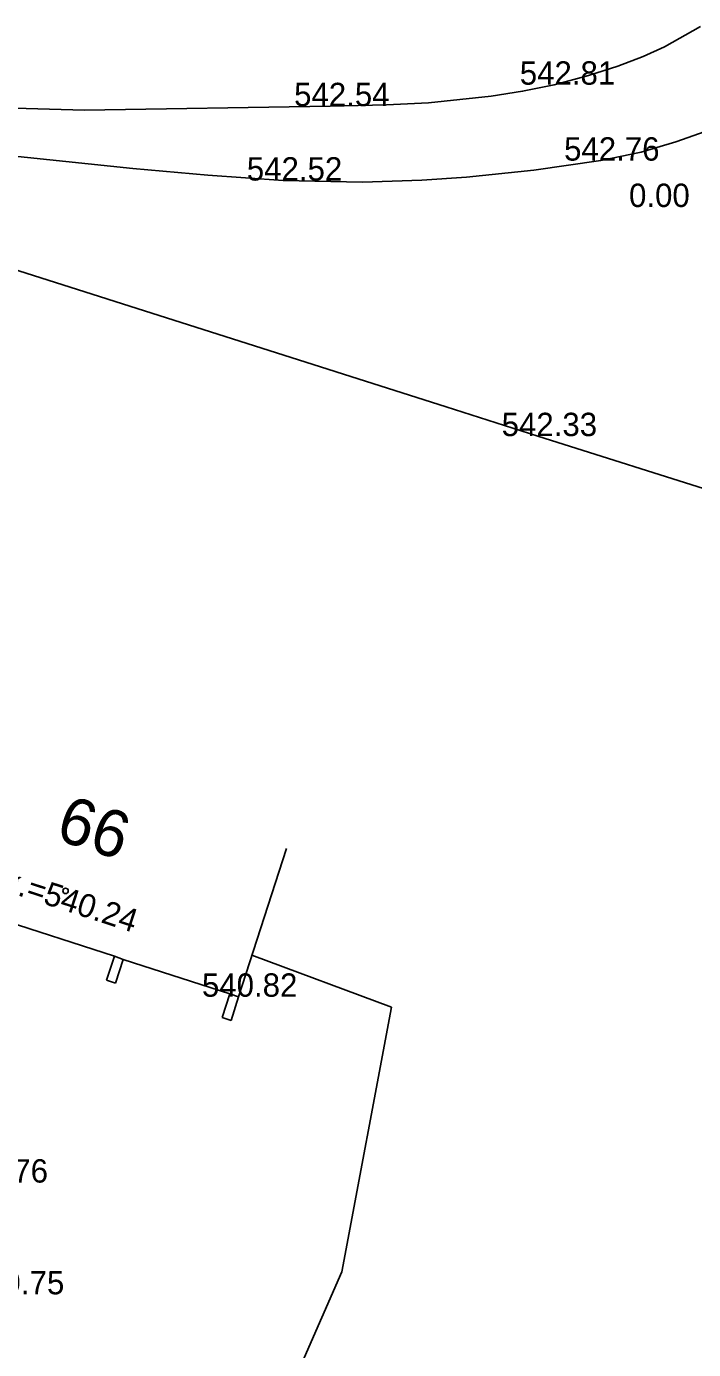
# Model space of a CAD drawing. Extents: x -669393 to -668650, y -1126925 to -1126294.
# Drawn here: x -669060.59 to -669039.15, y -1126670.25 to -1126627.75 of the extents above; entities that cross this region are included whole.
import ezdxf

# ---------------------------------------------------------------- set-up
doc = ezdxf.new("R2010")
doc.units = 0
for name, color, linetype in [('G_Bod_tecka', 7, 'Continuous'), ('G_Bod_vyska', 7, 'Continuous'), ('G_Budovy-znacky', 7, 'Continuous'), ('G_Budovy_Objekty', 7, 'Continuous'), ('G_Budovy_vstupy', 7, 'Continuous'), ('G_Cesty_Schody', 7, 'Continuous'), ('G_Cisla_orientacni', 7, 'Continuous'), ('G_Ploty', 7, 'Continuous'), ('G_Poznamky_odkaz', 7, 'Continuous'), ('G_Z_SPOJE_podz_geodeticky', 7, 'Continuous'), ('G_Z_SPOJE_podz_kotovane', 7, 'Continuous'), ('G_Z_SPOJE_podz_priblizne', 7, 'Continuous')]:
    doc.layers.add(name, color=color, linetype=linetype)

msp = doc.modelspace()

# ---------------------------------------------------------------- linework, layer by layer
at = {"layer": 'G_Bod_tecka'}
for p, q in [((-669043.63, -1126629.62), (-669043.63, -1126629.62)), ((-669050.82, -1126630.31), (-669050.82, -1126630.31)), ((-669042.13, -1126632.06), (-669042.13, -1126632.06)), ((-669052.34, -1126632.7), (-669052.34, -1126632.7)), ((-669040.44, -1126633.55), (-669040.44, -1126633.55)), ((-669044.15, -1126640.91), (-669044.15, -1126640.91)), ((-669053.77, -1126658.92), (-669053.77, -1126658.92))]:
    msp.add_line(p, q, dxfattribs=at)
at = {"layer": 'G_Budovy-znacky'}
msp.add_circle((-669059.33, -1126655.52), 0.0875, dxfattribs=at)
at = {"layer": 'G_Budovy_Objekty'}
for p, q in [((-669052.23, -1126654.16), (-669053.77, -1126658.92)), ((-669065.11, -1126655.24), (-669057.76, -1126657.62)), ((-669057.76, -1126657.62), (-669057.48, -1126657.72)), ((-669057.48, -1126657.72), (-669054.05, -1126658.83)), ((-669054.05, -1126658.83), (-669053.77, -1126658.92))]:
    msp.add_line(p, q, dxfattribs=at)
at = {"layer": 'G_Budovy_vstupy'}
msp.add_line((-669044.15, -1126640.91), (-669047.1, -1126639.97), dxfattribs=at)
at = {"layer": 'G_Cesty_Schody'}
for points in [[(-669061.35, -1126630.36), (-669058.72, -1126630.44), (-669050.82, -1126630.31), (-669049.02, -1126630.27), (-669047.67, -1126630.2), (-669045.65, -1126629.99), (-669044.64, -1126629.83), (-669043.63, -1126629.62), (-669042.52, -1126629.33), (-669041.58, -1126629.03), (-669040.77, -1126628.71), (-669040.08, -1126628.4), (-669038.92, -1126627.75)], [(-669062, -1126631.81), (-669057.17, -1126632.31), (-669054.76, -1126632.53), (-669052.34, -1126632.7), (-669049.79, -1126632.75), (-669047.88, -1126632.69), (-669046.44, -1126632.59), (-669044.28, -1126632.37), (-669042.13, -1126632.06), (-669040.83, -1126631.79), (-669039.72, -1126631.46), (-669038.77, -1126631.12)]]:
    msp.add_lwpolyline(points, dxfattribs=at)
at = {"layer": 'G_Ploty'}
for p, q in [((-669065.32, -1126634.17), (-669047.1, -1126639.97)), ((-669044.15, -1126640.91), (-669036.24, -1126643.41)), ((-669058.01, -1126658.39), (-669057.76, -1126657.62)), ((-669057.72, -1126658.48), (-669057.48, -1126657.72)), ((-669058.01, -1126658.39), (-669057.72, -1126658.48)), ((-669054.3, -1126659.59), (-669054.05, -1126658.83)), ((-669054.01, -1126659.68), (-669053.77, -1126658.92)), ((-669054.3, -1126659.59), (-669054.01, -1126659.68))]:
    msp.add_line(p, q, dxfattribs=at)
at = {"layer": 'G_Z_SPOJE_podz_geodeticky'}
for points in [[(-669053.34, -1126657.59), (-669048.85, -1126659.26)], [(-669042.14, -1126711.66), (-669042.16, -1126710.8), (-669048.67, -1126701.76), (-669050.99, -1126698.94), (-669051.74, -1126696.72), (-669052.32, -1126693.14), (-669051.84, -1126691.33), (-669051.61, -1126689.78), (-669050.9, -1126687.48), (-669053.66, -1126675.09), (-669050.45, -1126667.76), (-669048.85, -1126659.26)]]:
    msp.add_lwpolyline(points, dxfattribs=at)
at = {"layer": 'G_Z_SPOJE_podz_kotovane'}
for points in [[(-669053.34, -1126657.59), (-669048.85, -1126659.26)], [(-669042.14, -1126711.66), (-669042.16, -1126710.8), (-669048.67, -1126701.76), (-669050.99, -1126698.94), (-669051.74, -1126696.72), (-669052.32, -1126693.14), (-669051.84, -1126691.33), (-669051.61, -1126689.78), (-669050.9, -1126687.48), (-669053.66, -1126675.09), (-669050.45, -1126667.76), (-669048.85, -1126659.26)]]:
    msp.add_lwpolyline(points, dxfattribs=at)
at = {"layer": 'G_Z_SPOJE_podz_priblizne'}
for points in [[(-669053.34, -1126657.59), (-669048.85, -1126659.26)], [(-669042.14, -1126711.66), (-669042.16, -1126710.8), (-669048.67, -1126701.76), (-669050.99, -1126698.94), (-669051.74, -1126696.72), (-669052.32, -1126693.14), (-669051.84, -1126691.33), (-669051.61, -1126689.78), (-669050.9, -1126687.48), (-669053.66, -1126675.09), (-669050.45, -1126667.76), (-669048.85, -1126659.26)]]:
    msp.add_lwpolyline(points, dxfattribs=at)

# ---------------------------------------------------------------- texts
at = {"layer": 'G_Bod_vyska'}
for s, p in [('542.81', (-669044.732, -1126629.62)), ('542.54', (-669051.984, -1126630.31)), ('542.76', (-669043.308, -1126632.06)), ('542.52', (-669053.504, -1126632.7)), ('0.00', (-669041.22, -1126633.55)), ('542.33', (-669045.314, -1126640.91)), ('540.82', (-669054.946, -1126658.92)), ('539.76', (-669062.96, -1126664.89)), ('539.75', (-669062.436, -1126668.48))]:
    msp.add_text(s, height=0.75, dxfattribs=at).set_placement(p)
at = {"layer": 'G_Cisla_orientacni'}
msp.add_text('66', height=1.5, rotation=342.0484, dxfattribs=at).set_placement((-669059.699, -1126653.85))
at = {"layer": 'G_Poznamky_odkaz'}
msp.add_text('Pø.=540.24', height=0.75, rotation=342.0509, dxfattribs=at).set_placement((-669062.123, -1126655.26))

doc.saveas('drawing.dxf')
